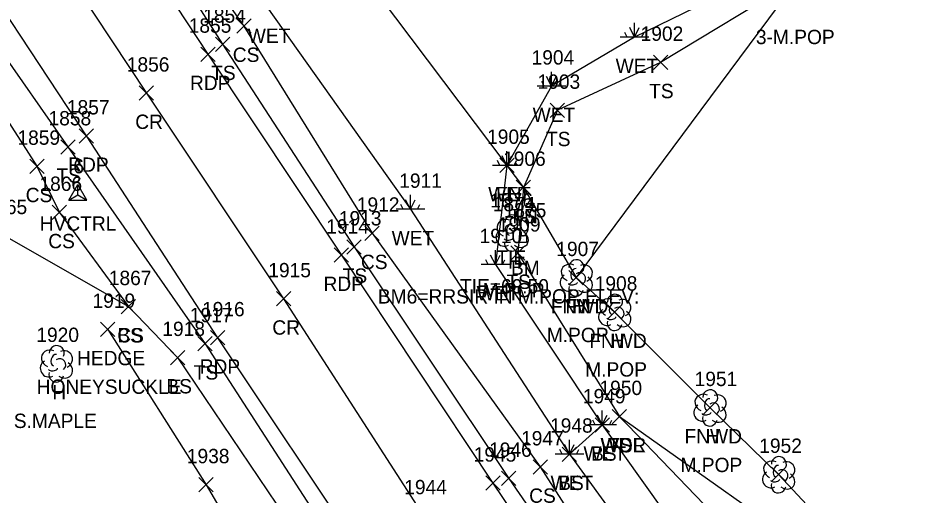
# Model space of a CAD drawing. Extents: x 1501299 to 1502485, y 381423 to 383765.
# Drawn here: x 1501473.5 to 1501597.6, y 383431.6 to 383498.2 of the extents above; entities that cross this region are included whole.
import ezdxf

# ---------------------------------------------------------------- set-up
doc = ezdxf.new("R2010")
doc.units = 0
for name, color, linetype in [('C_A', 7, 'Continuous'), ('C_C', 7, 'Continuous'), ('C_I', 7, 'Continuous'), ('CBP', 7, 'Continuous'), ('CPBM', 7, 'Continuous'), ('CPSM', 7, 'Continuous'), ('L_A', 7, 'Continuous'), ('L_C', 7, 'Continuous'), ('L_I', 7, 'Continuous'), ('L_TIC', 7, 'Continuous'), ('LAHR', 7, 'Continuous'), ('LAWA', 7, 'Continuous'), ('LELB', 7, 'Continuous'), ('LFNC', 7, 'Continuous'), ('LTD', 7, 'Continuous'), ('LWET', 7, 'Continuous'), ('P_A', 7, 'Continuous'), ('P_I', 7, 'Continuous'), ('P_TIC', 7, 'Continuous'), ('PET', 7, 'Continuous'), ('PRC', 7, 'Continuous')]:
    doc.layers.add(name, color=color, linetype=linetype)

msp = doc.modelspace()

# ---------------------------------------------------------------- linework, layer by layer
at = {"layer": 'CBP'}
for radius in [0.625, 0.0833]:
    msp.add_circle((1501542.19, 383468.75), radius, dxfattribs=at)
at = {"layer": 'CPBM'}
for p, q in [((1501543.5, 383466.84), (1501543.5, 383467.84)), ((1501543.5, 383467.84), (1501544.5, 383467.84)), ((1501544.01, 383467.34), (1501544.01, 383467.34)), ((1501544.01, 383467.34), (1501544.01, 383467.34)), ((1501544.5, 383467.84), (1501544.5, 383466.84)), ((1501544.5, 383466.84), (1501543.5, 383466.84))]:
    msp.add_line(p, q, dxfattribs=at)
at = {"layer": 'CPSM'}
for p, q in [((1501480.62, 383472.78), (1501481.87, 383474.95)), ((1501483.12, 383472.78), (1501481.87, 383474.95)), ((1501481.87, 383473.5), (1501481.87, 383474.95)), ((1501480.62, 383472.78), (1501481.87, 383473.5)), ((1501481.87, 383473.5), (1501481.87, 383473.5)), ((1501481.87, 383473.5), (1501483.12, 383472.78)), ((1501480.62, 383472.78), (1501483.12, 383472.78))]:
    msp.add_line(p, q, dxfattribs=at)
at = {"layer": 'L_TIC'}
for points in [[(1501504.06, 383496.04), (1501506.06, 383498.04)], [(1501506.06, 383496.04), (1501504.06, 383498.04)], [(1501501.07, 383493.51), (1501503.07, 383495.51)], [(1501503.07, 383493.51), (1501501.07, 383495.51)], [(1501562.19, 383490.98), (1501564.19, 383492.98)], [(1501564.19, 383490.98), (1501562.19, 383492.98)], [(1501547.8, 383484.29), (1501549.8, 383486.29)], [(1501549.8, 383484.29), (1501547.8, 383486.29)], [(1501479.49, 383479.19), (1501481.49, 383481.19)], [(1501481.49, 383479.19), (1501479.49, 383481.19)], [(1501475.16, 383476.48), (1501477.16, 383478.48)], [(1501477.16, 383476.48), (1501475.16, 383478.48)], [(1501540.76, 383476.61), (1501542.76, 383478.61)], [(1501542.76, 383476.61), (1501540.76, 383478.61)], [(1501543.05, 383473.54), (1501545.05, 383475.54)], [(1501545.05, 383473.54), (1501543.05, 383475.54)], [(1501543.05, 383473.54), (1501545.05, 383475.54)], [(1501545.05, 383473.54), (1501543.05, 383475.54)], [(1501478.31, 383470.05), (1501480.31, 383472.05)], [(1501480.31, 383470.05), (1501478.31, 383472.05)], [(1501521.93, 383467.15), (1501523.93, 383469.15)], [(1501523.93, 383467.15), (1501521.93, 383469.15)], [(1501519.43, 383465.23), (1501521.43, 383467.23)], [(1501521.43, 383465.23), (1501519.43, 383467.23)], [(1501542.28, 383464.38), (1501544.28, 383466.38)], [(1501544.28, 383464.38), (1501542.28, 383466.38)], [(1501550.42, 383460.96), (1501552.42, 383462.96)], [(1501552.42, 383460.96), (1501550.42, 383462.96)], [(1501550.42, 383460.96), (1501552.42, 383462.96)], [(1501552.42, 383460.96), (1501550.42, 383462.96)], [(1501487.94, 383456.91), (1501489.94, 383458.91)], [(1501489.94, 383456.91), (1501487.94, 383458.91)], [(1501487.94, 383456.91), (1501489.94, 383458.91)], [(1501489.94, 383456.91), (1501487.94, 383458.91)], [(1501555.79, 383456.15), (1501557.79, 383458.15)], [(1501557.79, 383456.15), (1501555.79, 383458.15)], [(1501485.06, 383453.74), (1501487.06, 383455.74)], [(1501487.06, 383453.74), (1501485.06, 383455.74)], [(1501498.63, 383451.74), (1501500.63, 383453.74)], [(1501500.63, 383451.74), (1501498.63, 383453.74)], [(1501494.79, 383449.81), (1501496.79, 383451.81)], [(1501496.79, 383449.81), (1501494.79, 383451.81)], [(1501569.08, 383442.83), (1501571.08, 383444.83)], [(1501571.08, 383442.83), (1501569.08, 383444.83)], [(1501556.45, 383441.58), (1501558.45, 383443.58)], [(1501558.45, 383441.58), (1501556.45, 383443.58)], [(1501556.45, 383441.58), (1501558.45, 383443.58)], [(1501558.45, 383441.58), (1501556.45, 383443.58)], [(1501556.45, 383441.58), (1501558.45, 383443.58)], [(1501558.45, 383441.58), (1501556.45, 383443.58)], [(1501554.06, 383440.42), (1501556.06, 383442.42)], [(1501556.06, 383440.42), (1501554.06, 383442.42)], [(1501549.47, 383436.33), (1501551.47, 383438.33)], [(1501551.47, 383436.33), (1501549.47, 383438.33)], [(1501545.42, 383434.55), (1501547.42, 383436.55)], [(1501547.42, 383434.55), (1501545.42, 383436.55)], [(1501541.02, 383432.96), (1501543.02, 383434.96)], [(1501543.02, 383432.96), (1501541.02, 383434.96)], [(1501578.66, 383433.51), (1501580.66, 383435.51)], [(1501580.66, 383433.51), (1501578.66, 383435.51)], [(1501498.78, 383432.07), (1501500.78, 383434.07)], [(1501500.78, 383432.07), (1501498.78, 383434.07)]]:
    msp.add_lwpolyline(points, dxfattribs=at)
at = {"layer": 'LAHR'}
msp.add_lwpolyline([(1501486.06, 383454.74), (1501499.78, 383433.07), (1501510.07, 383415.46)], dxfattribs=at)
at = {"layer": 'LAWA'}
for points in [[(1501557.45, 383442.58), (1501575.15, 383424.23), (1501579.77, 383412.79), (1501600.51, 383374.82), (1501609.72, 383369.18), (1501618.19, 383374.12), (1501605.62, 383397.42)], [(1501557.45, 383442.58), (1501587.95, 383421), (1501605.62, 383397.42)]]:
    msp.add_lwpolyline(points, dxfattribs=at)
at = {"layer": 'LELB'}
for points in [[(1501358.62, 383732.98), (1501381.14, 383696.09), (1501398.69, 383667.71), (1501415.46, 383640.29), (1501435.3, 383603.99), (1501464.9, 383561.23), (1501485.32, 383525.1), (1501505.06, 383497.04), (1501522.93, 383468.15), (1501546.42, 383435.55), (1501564.6, 383407.15), (1501589.27, 383369.8), (1501600.38, 383363.76)], [(1501355.51, 383731.14), (1501378.37, 383693.86), (1501395.55, 383665.66), (1501411.45, 383638.21), (1501433.32, 383602.63), (1501461.34, 383558.64), (1501483.16, 383524.05), (1501502.07, 383494.51), (1501520.43, 383466.23), (1501542.02, 383433.96), (1501561.69, 383405.4), (1501588.28, 383366.16), (1501592.45, 383361.85)], [(1501332.79, 383719.08), (1501356.21, 383681.5), (1501373.29, 383652.69), (1501388.57, 383624.23), (1501410.59, 383588.65), (1501439.07, 383543.46), (1501460.07, 383509.46), (1501480.49, 383480.19), (1501499.63, 383452.74), (1501519.17, 383422.52), (1501533.38, 383399.88)], [(1501410.59, 383588.65), (1501435.97, 383541.32), (1501457.1, 383507.19), (1501476.16, 383477.48), (1501479.31, 383471.05), (1501488.94, 383457.91)], [(1501582.32, 383503.52), (1501563.19, 383491.98), (1501548.8, 383485.29), (1501544.05, 383474.54), (1501543.28, 383465.38), (1501557.45, 383442.58)], [(1501466.9, 383480.31), (1501471.6, 383467.81), (1501488.94, 383457.91), (1501495.79, 383450.81), (1501515.89, 383421.07), (1501517.94, 383408.26), (1501520.75, 383388.81), (1501512.36, 383377.31), (1501492.52, 383361.6), (1501470.5, 383349.33), (1501449.88, 383345.74), (1501440.32, 383348.07)], [(1501555.06, 383441.42), (1501575.01, 383413.45), (1501600.51, 383374.82)], [(1501550.47, 383437.33), (1501569.88, 383410.61), (1501593.86, 383372.66), (1501600.38, 383363.76), (1501609.16, 383365.94), (1501620.09, 383370.75), (1501635.69, 383377), (1501648.8, 383391.86)]]:
    msp.add_lwpolyline(points, dxfattribs=at)
at = {"layer": 'LFNC'}
for points in [[(1501374.37, 383742.56), (1501382.94, 383727.21), (1501403.34, 383685.19), (1501409.51, 383674.58), (1501426.09, 383647.98), (1501436.22, 383631.2), (1501450.55, 383610.14), (1501477.09, 383568.96), (1501495.83, 383538.88), (1501500.46, 383533.1), (1501519.53, 383507.11), (1501541.76, 383477.61), (1501544.05, 383474.54), (1501551.42, 383461.96)], [(1501598.42, 383526.97), (1501583.57, 383507.22), (1501582.32, 383503.52), (1501551.42, 383461.96), (1501556.79, 383457.15), (1501570.08, 383443.83), (1501579.66, 383434.51), (1501590.93, 383422.47), (1501618.03, 383406.52), (1501631.82, 383398.73), (1501638.24, 383395.91), (1501648.8, 383391.86), (1501655.59, 383390.21)]]:
    msp.add_lwpolyline(points, dxfattribs=at)
at = {"layer": 'LTD'}
for p, q in [((1501542.47, 383468.21), (1501542.47, 383468.21)), ((1501542.47, 383468.21), (1501542.47, 383468.21)), ((1501551.42, 383461.96), (1501551.42, 383461.96)), ((1501551.42, 383461.96), (1501551.42, 383461.96)), ((1501556.79, 383457.15), (1501556.79, 383457.15)), ((1501556.79, 383457.15), (1501556.79, 383457.15)), ((1501478.87, 383449.98), (1501478.87, 383449.98)), ((1501478.87, 383449.98), (1501478.87, 383449.98)), ((1501570.08, 383443.83), (1501570.08, 383443.83)), ((1501570.08, 383443.83), (1501570.08, 383443.83)), ((1501579.66, 383434.51), (1501579.66, 383434.51)), ((1501579.66, 383434.51), (1501579.66, 383434.51))]:
    msp.add_line(p, q, dxfattribs=at)
for centre in [(1501542.51, 383469.65), (1501551.47, 383463.4), (1501556.83, 383458.59), (1501478.92, 383451.42), (1501570.13, 383445.26), (1501579.71, 383435.94)]:
    msp.add_arc(centre, 1.05, 335.5272, 180.9563, dxfattribs=at)
for centre, major_axis, ratio, start_param, end_param in [((1501541.68, 383468.88), (1.21, -0.51), 0.895232, 1.570796, 4.712389), ((1501542.26, 383468.67), (-0.208, -0.792), 0.645439, 3.141593, 6.283185), ((1501543.51, 383468.8), (-1.14, -0.48), 0.949671, 1.570796, 4.712389), ((1501541.38, 383467.5), (0.58, -1.04), 0.959034, 3.141593, 6.283185), ((1501542.97, 383468.05), (-0.5, 0.667), 0.989748, 3.141593, 6.283185), ((1501543.47, 383467.38), (-1.09, 0.79), 0.841452, 1.570796, 4.712389), ((1501542.47, 383466.71), (0.26, 1.06), 0.942809, 1.570796, 4.712389), ((1501542.01, 383467.46), (-0.625, -0.083), 0.423636, 0, 3.141593), ((1501550.63, 383462.63), (1.21, -0.51), 0.895232, 1.570796, 4.712389), ((1501551.21, 383462.42), (-0.208, -0.792), 0.645439, 3.141593, 6.283185), ((1501552.46, 383462.55), (-1.14, -0.48), 0.949671, 1.570796, 4.712389), ((1501550.34, 383461.25), (0.58, -1.04), 0.959034, 3.141593, 6.283185), ((1501551.92, 383461.8), (-0.5, 0.667), 0.989748, 3.141593, 6.283185), ((1501552.42, 383461.13), (-1.09, 0.79), 0.841452, 1.570796, 4.712389), ((1501551.42, 383460.46), (0.26, 1.06), 0.942809, 1.570796, 4.712389), ((1501550.96, 383461.21), (-0.625, -0.083), 0.423636, 0, 3.141593), ((1501555.99, 383457.82), (1.21, -0.51), 0.895232, 1.570796, 4.712389), ((1501556.58, 383457.61), (-0.208, -0.792), 0.645439, 3.141593, 6.283185), ((1501557.83, 383457.74), (-1.14, -0.48), 0.949671, 1.570796, 4.712389), ((1501555.7, 383456.44), (0.58, -1.04), 0.959034, 3.141593, 6.283185), ((1501557.29, 383456.99), (-0.5, 0.667), 0.989748, 3.141593, 6.283185), ((1501557.79, 383456.32), (-1.09, 0.79), 0.841452, 1.570796, 4.712389), ((1501556.79, 383455.65), (0.26, 1.06), 0.942809, 1.570796, 4.712389), ((1501556.33, 383456.4), (-0.625, -0.083), 0.423636, 0, 3.141593), ((1501478.08, 383450.65), (1.21, -0.51), 0.895232, 1.570796, 4.712389), ((1501478.67, 383450.44), (-0.208, -0.792), 0.645439, 3.141593, 6.283185), ((1501479.37, 383449.82), (-0.5, 0.667), 0.989748, 3.141593, 6.283185), ((1501479.92, 383450.57), (-1.14, -0.48), 0.949671, 1.570796, 4.712389), ((1501477.79, 383449.27), (0.58, -1.04), 0.959034, 3.141593, 6.283185), ((1501479.87, 383449.15), (-1.09, 0.79), 0.841452, 1.570796, 4.712389), ((1501478.87, 383448.48), (0.26, 1.06), 0.942809, 1.570796, 4.712389), ((1501478.42, 383449.23), (-0.625, -0.083), 0.423636, 0, 3.141593), ((1501569.29, 383444.49), (1.21, -0.51), 0.895232, 1.570796, 4.712389), ((1501571.12, 383444.41), (-1.14, -0.48), 0.949671, 1.570796, 4.712389), ((1501569.87, 383444.28), (-0.208, -0.792), 0.645439, 3.141593, 6.283185), ((1501570.58, 383443.66), (-0.5, 0.667), 0.989748, 3.141593, 6.283185), ((1501569, 383443.12), (0.58, -1.04), 0.959034, 3.141593, 6.283185), ((1501571.08, 383442.99), (-1.09, 0.79), 0.841452, 1.570796, 4.712389), ((1501570.08, 383442.33), (0.26, 1.06), 0.942809, 1.570796, 4.712389), ((1501569.62, 383443.08), (-0.625, -0.083), 0.423636, 0, 3.141593), ((1501578.87, 383435.18), (1.21, -0.51), 0.895232, 1.570796, 4.712389), ((1501579.45, 383434.97), (-0.208, -0.792), 0.645439, 3.141593, 6.283185), ((1501580.7, 383435.09), (-1.14, -0.48), 0.949671, 1.570796, 4.712389), ((1501578.58, 383433.8), (0.58, -1.04), 0.959034, 3.141593, 6.283185), ((1501580.16, 383434.34), (-0.5, 0.667), 0.989748, 3.141593, 6.283185), ((1501580.66, 383433.68), (-1.09, 0.79), 0.841452, 1.570796, 4.712389), ((1501579.2, 383433.76), (-0.625, -0.083), 0.423636, 0, 3.141593), ((1501579.66, 383433.01), (0.26, 1.06), 0.942809, 1.570796, 4.712389)]:
    msp.add_ellipse(centre, major_axis=major_axis, ratio=ratio, start_param=start_param, end_param=end_param, dxfattribs=at)
at = {"layer": 'LWET'}
for p, q in [((1501559.55, 383495.49), (1501558.89, 383496.83)), ((1501559.55, 383495.49), (1501559.55, 383497.49)), ((1501559.55, 383495.49), (1501560.22, 383496.83)), ((1501561.55, 383495.49), (1501557.55, 383495.49)), ((1501558.55, 383495.49), (1501558.22, 383496.16)), ((1501560.55, 383495.49), (1501560.89, 383496.16)), ((1501547.97, 383488.67), (1501547.97, 383490.67)), ((1501546.97, 383488.67), (1501546.63, 383489.33)), ((1501547.97, 383488.67), (1501547.3, 383490)), ((1501547.97, 383488.67), (1501548.63, 383490)), ((1501548.97, 383488.67), (1501549.3, 383489.33)), ((1501549.97, 383488.67), (1501545.97, 383488.67)), ((1501541.76, 383477.61), (1501541.76, 383479.61)), ((1501540.76, 383477.61), (1501540.43, 383478.28)), ((1501541.76, 383477.61), (1501541.1, 383478.95)), ((1501541.76, 383477.61), (1501542.43, 383478.95)), ((1501542.76, 383477.61), (1501543.1, 383478.28)), ((1501543.76, 383477.61), (1501539.76, 383477.61)), ((1501528.29, 383471.48), (1501528.29, 383473.48)), ((1501527.29, 383471.48), (1501526.96, 383472.15)), ((1501528.29, 383471.48), (1501527.62, 383472.82)), ((1501528.29, 383471.48), (1501528.96, 383472.82)), ((1501529.29, 383471.48), (1501529.62, 383472.15)), ((1501530.29, 383471.48), (1501526.29, 383471.48)), ((1501540.15, 383463.77), (1501540.15, 383465.77)), ((1501539.15, 383463.77), (1501538.82, 383464.44)), ((1501540.15, 383463.77), (1501539.48, 383465.1)), ((1501540.15, 383463.77), (1501540.82, 383465.1)), ((1501541.15, 383463.77), (1501541.48, 383464.44)), ((1501542.15, 383463.77), (1501538.15, 383463.77)), ((1501555.06, 383441.42), (1501555.06, 383443.42)), ((1501555.06, 383441.42), (1501555.06, 383443.42)), ((1501554.06, 383441.42), (1501553.73, 383442.09)), ((1501554.06, 383441.42), (1501553.73, 383442.09)), ((1501555.06, 383441.42), (1501554.4, 383442.76)), ((1501555.06, 383441.42), (1501554.4, 383442.76)), ((1501555.06, 383441.42), (1501555.73, 383442.76)), ((1501555.06, 383441.42), (1501555.73, 383442.76)), ((1501556.06, 383441.42), (1501556.4, 383442.09)), ((1501556.06, 383441.42), (1501556.4, 383442.09)), ((1501557.06, 383441.42), (1501553.06, 383441.42)), ((1501557.06, 383441.42), (1501553.06, 383441.42)), ((1501550.47, 383437.33), (1501549.81, 383438.66)), ((1501550.47, 383437.33), (1501550.47, 383439.33)), ((1501550.47, 383437.33), (1501551.14, 383438.66)), ((1501552.47, 383437.33), (1501548.47, 383437.33)), ((1501549.47, 383437.33), (1501549.14, 383438)), ((1501551.47, 383437.33), (1501551.81, 383438))]:
    msp.add_line(p, q, dxfattribs=at)
for points in [[(1501361.86, 383735.32), (1501383.52, 383697.56), (1501401.54, 383668.95), (1501420.14, 383643.24), (1501429.42, 383625.36), (1501440.42, 383606.65), (1501468.13, 383563.3), (1501489.26, 383528.35), (1501508.23, 383499.7), (1501528.29, 383471.48), (1501550.47, 383437.33), (1501555.06, 383441.42)], [(1501583.57, 383507.22), (1501559.55, 383495.49), (1501547.97, 383488.67), (1501541.76, 383477.61), (1501540.15, 383463.77), (1501555.06, 383441.42)]]:
    msp.add_lwpolyline(points, dxfattribs=at)
at = {"layer": 'P_TIC'}
for points in [[(1501499.04, 383492.11), (1501501.04, 383494.11)], [(1501501.04, 383492.11), (1501499.04, 383494.11)], [(1501490.45, 383486.69), (1501492.45, 383488.69)], [(1501492.45, 383486.69), (1501490.45, 383488.69)], [(1501482.05, 383480.71), (1501484.05, 383482.71)], [(1501484.05, 383480.71), (1501482.05, 383482.71)], [(1501517.67, 383464.09), (1501519.67, 383466.09)], [(1501519.67, 383464.09), (1501517.67, 383466.09)], [(1501509.59, 383458), (1501511.59, 383460)], [(1501511.59, 383458), (1501509.59, 383460)], [(1501500.39, 383452.56), (1501502.39, 383454.56)], [(1501502.39, 383452.56), (1501500.39, 383454.56)], [(1501538.81, 383432.29), (1501540.81, 383434.29)], [(1501540.81, 383432.29), (1501538.81, 383434.29)]]:
    msp.add_lwpolyline(points, dxfattribs=at)
at = {"layer": 'PET'}
for points in [[(1501352.61, 383730.1), (1501376.04, 383692.66), (1501392.89, 383664.45), (1501409.55, 383637.05), (1501431.22, 383601.01), (1501459.29, 383556.77), (1501480.73, 383522.39), (1501500.04, 383493.11), (1501518.67, 383465.09), (1501539.81, 383433.29), (1501559.66, 383403.85), (1501585.89, 383364.55), (1501607.04, 383333.42), (1501616.49, 383318.82), (1501608.79, 383312.41), (1501601.65, 383306.28)], [(1501334.83, 383720.25), (1501358.01, 383682.47), (1501375.27, 383653.98), (1501391.81, 383626.28), (1501413.67, 383590.16), (1501441.93, 383545.3), (1501463.31, 383511.64), (1501483.05, 383481.71), (1501501.39, 383453.56), (1501521.79, 383422.95), (1501532.7, 383406.6), (1501560.32, 383365.3), (1501580.55, 383335.85), (1501587.21, 383326.16), (1501601.65, 383306.28)]]:
    msp.add_lwpolyline(points, dxfattribs=at)
at = {"layer": 'PRC'}
msp.add_lwpolyline([(1501342.03, 383724.18), (1501367.31, 383687.9), (1501383.59, 383659.52), (1501401.02, 383631.48), (1501422.76, 383595.53), (1501451.02, 383550.58), (1501471.94, 383517.22), (1501491.45, 383487.69), (1501510.59, 383459), (1501530.12, 383428.74), (1501550.99, 383398.39), (1501579.41, 383355.49), (1501608.79, 383312.41)], dxfattribs=at)

# ---------------------------------------------------------------- texts
at = {"layer": 'C_A'}
for s, p in [('HVCTRL', (1501476.56, 383468.5)), ('TIE', (1501540.27, 383463.75)), ('BM', (1501542.32, 383462.34))]:
    msp.add_text(s, height=2, dxfattribs=at).set_placement(p)
at = {"layer": 'C_C'}
for s, p in [('TIE=60.50', (1501535.2, 383459.75)), ('BM6=RRSIR IN M.POP ELEV:', (1501523.75, 383458.34))]:
    msp.add_text(s, height=2, dxfattribs=at).set_placement(p)
at = {"layer": 'C_I'}
for s, p in [('6', (1501481.25, 383476.5)), ('1876', (1501539.44, 383471.75)), ('1875', (1501541.31, 383470.34))]:
    msp.add_text(s, height=2, dxfattribs=at).set_placement(p)
at = {"layer": 'L_A'}
for s, p in [('WET', (1501505.6, 383494.7)), ('CS', (1501503.5, 383492.04)), ('WET', (1501556.93, 383490.49)), ('TS', (1501500.48, 383489.51)), ('TS', (1501561.6, 383486.98)), ('WET', (1501545.35, 383483.67)), ('TS', (1501547.21, 383480.29)), ('TS', (1501478.9, 383475.19)), ('CS', (1501474.6, 383472.48)), ('WET', (1501539.14, 383472.61)), ('FN', (1501540.24, 383472.61)), ('TS', (1501542.46, 383469.54)), ('FN', (1501542.53, 383469.54)), ('WET', (1501525.67, 383466.48)), ('CS', (1501477.75, 383466.05)), ('CS', (1501521.38, 383463.15)), ('H', (1501541.9, 383463.21)), ('TS', (1501518.84, 383461.23)), ('TS', (1501541.69, 383460.38)), ('WET', (1501537.53, 383458.77)), ('FNWD', (1501547.89, 383456.96)), ('FN', (1501549.9, 383456.96)), ('H', (1501550.86, 383456.96)), ('CS', (1501487.38, 383452.91)), ('BS', (1501487.38, 383452.91)), ('FNWD', (1501553.25, 383452.15)), ('H', (1501556.22, 383452.15)), ('HEDGE', (1501481.76, 383449.74)), ('TS', (1501498.04, 383447.74)), ('BS', (1501494.23, 383445.81)), ('H', (1501478.31, 383444.98)), ('FNWD', (1501566.54, 383438.83)), ('H', (1501569.51, 383438.83)), ('WDR', (1501554.81, 383437.58)), ('WDL', (1501554.87, 383437.58)), ('TS', (1501555.86, 383437.58)), ('WET', (1501552.44, 383436.42)), ('WET', (1501552.44, 383436.42)), ('BS', (1501553.5, 383436.42)), ('WET', (1501547.85, 383432.33)), ('BS', (1501548.91, 383432.33)), ('CS', (1501544.86, 383430.55))]:
    msp.add_text(s, height=2, dxfattribs=at).set_placement(p)
at = {"layer": 'L_C'}
for s, p in [('3-M.POP', (1501576.5, 383494.52)), ('M.POP', (1501538.37, 383459.21)), ('M.POP', (1501547.32, 383452.96)), ('M.POP', (1501552.68, 383448.15)), ('HONEYSUCKLE', (1501476.13, 383445.74)), ('S.MAPLE', (1501472.94, 383440.98)), ('M.POP', (1501565.98, 383434.83))]:
    msp.add_text(s, height=2, dxfattribs=at).set_placement(p)
at = {"layer": 'L_I'}
for s, p in [('1854', (1501499.37, 383497.51)), ('1902', (1501560.42, 383494.98)), ('1904', (1501545.2, 383491.67)), ('1903', (1501546.03, 383488.29)), ('1858', (1501477.79, 383483.19)), ('1859', (1501473.45, 383480.48)), ('1905', (1501538.99, 383480.61)), ('1905', (1501538.99, 383480.61)), ('1906', (1501541.22, 383477.54)), ('1906', (1501541.22, 383477.54)), ('1866', (1501476.52, 383474.05)), ('1911', (1501526.73, 383474.48)), ('1912', (1501520.81, 383471.15)), ('1874', (1501539.78, 383471.21)), ('1865', (1501468.86, 383470.81)), ('1913', (1501518.3, 383469.23)), ('1909', (1501540.5, 383468.38)), ('1910', (1501537.94, 383466.77)), ('1907', (1501548.65, 383464.96)), ('1907', (1501548.65, 383464.96)), ('1907', (1501548.65, 383464.96)), ('1867', (1501486.2, 383460.91)), ('1867', (1501486.2, 383460.91)), ('1908', (1501554.01, 383460.15)), ('1908', (1501554.01, 383460.15)), ('1919', (1501483.93, 383457.74)), ('1917', (1501497.51, 383455.74)), ('1918', (1501493.67, 383453.81)), ('1920', (1501476.09, 383452.98)), ('1951', (1501567.95, 383446.83)), ('1951', (1501567.95, 383446.83)), ('1950', (1501554.67, 383445.58)), ('1950', (1501554.67, 383445.58)), ('1950', (1501554.67, 383445.58)), ('1949', (1501552.36, 383444.42)), ('1949', (1501552.36, 383444.42)), ('1949', (1501552.36, 383444.42)), ('1948', (1501547.78, 383440.33)), ('1948', (1501547.78, 383440.33)), ('1947', (1501543.73, 383438.55)), ('1946', (1501539.27, 383436.96)), ('1952', (1501576.97, 383437.51)), ('1952', (1501576.97, 383437.51)), ('1938', (1501497.09, 383436.07))]:
    msp.add_text(s, height=2, dxfattribs=at).set_placement(p)
at = {"layer": 'P_A'}
for s, p in [('RDP', (1501497.53, 383488.11)), ('CR', (1501489.89, 383482.69)), ('RDP', (1501480.53, 383476.71)), ('RDP', (1501516.16, 383460.09)), ('CR', (1501509.02, 383454)), ('RDP', (1501498.88, 383448.56))]:
    msp.add_text(s, height=2, dxfattribs=at).set_placement(p)
at = {"layer": 'P_I'}
for s, p in [('1855', (1501497.35, 383496.11)), ('1856', (1501488.71, 383490.69)), ('1857', (1501480.35, 383484.71)), ('1914', (1501516.54, 383468.09)), ('1915', (1501508.46, 383462)), ('1916', (1501499.21, 383456.56)), ('1945', (1501537.12, 383436.29)), ('1944', (1501527.43, 383431.74))]:
    msp.add_text(s, height=2, dxfattribs=at).set_placement(p)

doc.saveas('drawing.dxf')
